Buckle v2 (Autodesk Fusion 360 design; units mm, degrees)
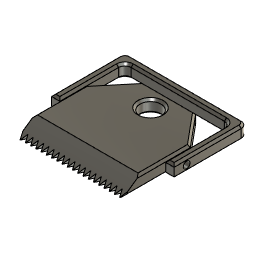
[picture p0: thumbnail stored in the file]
sketch "Sketch1" plane through (0, 0, 0) normal (0, 0, 1) x axis (1, 0, 0)
  line L1 (25, 30) -> (25, 0)
  line L2 (-25, 0) -> (-25, 30.0149)
  line L3 (-23.75, -2.5142) -> (-25, 0)
  line L4 (-22.5, 0) -> (-23.75, -2.5142)
  line L5 (-21.25, -2.5142) -> (-22.5, 0)
  line L6 (-20, 0) -> (-21.25, -2.5142)
  line L7 (-18.75, -2.5142) -> (-20, 0)
  line L8 (-17.5, 0) -> (-18.75, -2.5142)
  line L9 (-16.25, -2.5142) -> (-17.5, 0)
  line L10 (-15, 0) -> (-16.25, -2.5142)
  line L11 (-13.75, -2.5142) -> (-15, 0)
  line L12 (-12.5, 0) -> (-13.75, -2.5142)
  line L13 (-11.25, -2.5142) -> (-12.5, 0)
  line L14 (-10, 0) -> (-11.25, -2.5142)
  line L15 (-8.75, -2.5142) -> (-10, 0)
  line L16 (-7.5, 0) -> (-8.75, -2.5142)
  line L17 (-6.25, -2.5142) -> (-7.5, 0)
  line L18 (-5, 0) -> (-6.25, -2.5142)
  line L19 (-3.75, -2.5142) -> (-5, 0)
  line L20 (-2.5, 0) -> (-3.75, -2.5142)
  line L21 (-1.25, -2.5142) -> (-2.5, 0)
  line L22 (0, 0) -> (-1.25, -2.5142)
  line L23 (1.25, -2.5142) -> (0, 0)
  line L24 (2.5, 0) -> (1.25, -2.5142)
  line L25 (3.75, -2.5142) -> (2.5, 0)
  line L26 (5, 0) -> (3.75, -2.5142)
  line L27 (6.25, -2.5142) -> (5, 0)
  line L28 (7.5, 0) -> (6.25, -2.5142)
  line L29 (8.75, -2.5142) -> (7.5, 0)
  line L30 (10, 0) -> (8.75, -2.5142)
  line L31 (11.25, -2.5142) -> (10, 0)
  line L32 (12.5, 0) -> (11.25, -2.5142)
  line L33 (13.75, -2.5142) -> (12.5, 0)
  line L34 (15, 0) -> (13.75, -2.5142)
  line L35 (16.25, -2.5142) -> (15, 0)
  line L36 (17.5, 0) -> (16.25, -2.5142)
  line L37 (18.75, -2.5142) -> (17.5, 0)
  line L38 (20, 0) -> (18.75, -2.5142)
  line L39 (21.25, -2.5142) -> (20, 0)
  line L40 (22.5, 0) -> (21.25, -2.5142)
  line L41 (23.75, -2.5142) -> (22.5, 0)
  line L42 (25, 0) -> (23.75, -2.5142)
  line L43 (-12.491, 45) -> (-25, 30.0149)
  line L44 (12.509, 45) -> (-12.491, 45)
  line L45 (25, 30) -> (12.509, 45)
  circle C1 centre (-0.006, 36) radius 5
  point P66 (0.009, 45)
  point P1 (-25, 0)
  point P6 (-22.5, 0)
  point P3 (25, 30)
  point P64 (-12.491, 45)
  point P65 (12.509, 45)
  point P67 (-0.006, 36)
  point P2 (25, 0)
  vertical L1
  vertical L2
  equal L3 L4
  perpendicular L2 L44
  equal L43 L45
  midpoint L44 P66
  dimension "d1" distance P1 P6 = 2.5
  dimension "d6" distance P3 L44 = 15
  dimension "d7" distance L1 L2 = 50
  dimension "d8" distance P64 P65 = 25
  dimension "d9" diameter C1 = 10
  dimension "d10" distance P66 P67 = 9
  dimension "d11" distance P2 P3 = 30
  dimension "d4" R-Pattern1-uDistance = 47.5
  dimension "d5" R-Pattern1-vDistance = 0
extrude "Extrude1" new body sketch "Sketch1" along normal blind 6 bodies "Buckle"
sketch "Sketch2" plane through (-25, 0, 0) normal (-1, 0, 0) x axis (0, -1, 0)
  line L1 (0, 0) -> (-30.0149, 0)
  line L2 (0, 6) -> (0, 0)
  line L3 (-30.0149, 6) -> (0, 6)
  line L4 (-30.0149, 0) -> (-30.0149, 6)
  line L5 (2.5142, 0) -> (0, 0)
  line L6 (2.5142, 6) -> (2.5142, 0)
  line L7 (0, 6) -> (2.5142, 6)
  line L8 (0, 0) -> (0, 6)
  line L9 (0, 0) -> (2.5142, 0)
  line L10 (0, 6) -> (0, 0)
  line L11 (2.5142, 6) -> (0, 6)
  line L12 (2.5142, 0) -> (2.5142, 6)
  line L13 (-6.0547, 6) -> (2.5142, 0)
  line L14 (2.5142, 0) -> (-6.0547, 0)
  line L15 (-6.0547, 0) -> (-6.0547, 6)
  line L16 (2.5142, 6) -> (-6.0547, 6)
  point P7 (2.5142, 0)
  point P14 (2.5142, 0)
  point P15 (-6.0547, 6)
  point P16 (-6.0547, 0)
  point P17 (2.5142, 0)
  point P8 (2.5142, 6)
  point P18 (2.5142, 6)
  coincident P7 P14
  coincident L3 P15
  coincident L1 P16
  coincident P7 P17
  perpendicular L6 L14
  coincident P8 P18
  dimension "d14" angle L13 L14 = 35
  dimension "d15" angle L14 L15 = 90
extrude "Extrude2" cut sketch "Sketch2" profile of L2 L3 L6 L7 L8 L10 L11 L12 L13 L16 no distance stored
sketch "Sketch3" plane through (0, 0, 0) normal (0, 0, 1) x axis (1, 0, 0)
  line L1 (-25, 30.0149) -> (-25, 0)
  line L2 (-12.491, 45) -> (-25, 30.0149)
  line L3 (12.509, 45) -> (-12.491, 45)
  line L4 (25, 30) -> (12.509, 45)
  line L5 (25, 0) -> (25, 30)
  line L6 (23.75, -2.5142) -> (25, 0)
  line L7 (22.5, 0) -> (23.75, -2.5142)
  line L8 (21.25, -2.5142) -> (22.5, 0)
  line L9 (20, 0) -> (21.25, -2.5142)
  line L10 (18.75, -2.5142) -> (20, 0)
  line L11 (17.5, 0) -> (18.75, -2.5142)
  line L12 (16.25, -2.5142) -> (17.5, 0)
  line L13 (15, 0) -> (16.25, -2.5142)
  line L14 (13.75, -2.5142) -> (15, 0)
  line L15 (12.5, 0) -> (13.75, -2.5142)
  line L16 (11.25, -2.5142) -> (12.5, 0)
  line L17 (10, 0) -> (11.25, -2.5142)
  line L18 (8.75, -2.5142) -> (10, 0)
  line L19 (7.5, 0) -> (8.75, -2.5142)
  line L20 (6.25, -2.5142) -> (7.5, 0)
  line L21 (5, 0) -> (6.25, -2.5142)
  line L22 (3.75, -2.5142) -> (5, 0)
  line L23 (2.5, 0) -> (3.75, -2.5142)
  line L24 (1.25, -2.5142) -> (2.5, 0)
  line L25 (0, 0) -> (1.25, -2.5142)
  line L26 (-1.25, -2.5142) -> (0, 0)
  line L27 (-2.5, 0) -> (-1.25, -2.5142)
  line L28 (-3.75, -2.5142) -> (-2.5, 0)
  line L29 (-5, 0) -> (-3.75, -2.5142)
  line L30 (-6.25, -2.5142) -> (-5, 0)
  line L31 (-7.5, 0) -> (-6.25, -2.5142)
  line L32 (-8.75, -2.5142) -> (-7.5, 0)
  line L33 (-10, 0) -> (-8.75, -2.5142)
  line L34 (-11.25, -2.5142) -> (-10, 0)
  line L35 (-12.5, 0) -> (-11.25, -2.5142)
  line L36 (-13.75, -2.5142) -> (-12.5, 0)
  line L37 (-15, 0) -> (-13.75, -2.5142)
  line L38 (-16.25, -2.5142) -> (-15, 0)
  line L39 (-17.5, 0) -> (-16.25, -2.5142)
  line L40 (-18.75, -2.5142) -> (-17.5, 0)
  line L41 (-20, 0) -> (-18.75, -2.5142)
  line L42 (-21.25, -2.5142) -> (-20, 0)
  line L43 (-22.5, 0) -> (-21.25, -2.5142)
  line L44 (-23.75, -2.5142) -> (-22.5, 0)
  line L45 (-25, 0) -> (-23.75, -2.5142)
  line L46 (29.25, 18) -> (25.25, 18)
  line L47 (29.25, 54) -> (29.25, 18)
  line L48 (25.25, 18) -> (25.25, 49)
  line L49 (29.25, 54) -> (29.25, 53)
  line L50 (0, 49) -> (25.25, 49)
  line L51 (0, 53) -> (0, 49)
  line L52 (29.25, 53) -> (0, 53)
  line L53 (29.25, 54) -> (29.25, 53)
  line L54 (0, 72) -> (0, 0)
  line L55 (-29.25, 53) -> (0, 53)
  line L56 (0, 49) -> (-25.25, 49)
  line L57 (-25.25, 18) -> (-25.25, 49)
  line L58 (-29.25, 54) -> (-29.25, 18)
  line L59 (-29.25, 54) -> (-29.25, 53)
  line L60 (-29.25, 18) -> (-25.25, 18)
  circle C1 centre (-0.006, 36) radius 5
  point P28 (0, 0)
  point P56 (0, 0)
  point P48 (25.25, 18)
  point P62 (-25.25, 18)
  point P49 (29.25, 18)
  point P63 (-29.25, 18)
  point P50 (29.25, 54)
  point P64 (-29.25, 54)
  point P51 (25.25, 49)
  point P60 (-25.25, 49)
  point P53 (0, 49)
  point P61 (0, 49)
  point P54 (0, 53)
  point P58 (0, 53)
  point P55 (29.25, 53)
  point P59 (-29.25, 53)
  point P7 (25, 30)
  horizontal L46
  vertical L47
  vertical L48
  vertical L49
  horizontal L50
  vertical L51
  horizontal L52
  vertical L53
  coincident P28 P56
  perpendicular L52 L54
  symmetric P48 L54 P62
  symmetric P49 L54 P63
  symmetric P50 L54 P64
  symmetric P51 L54 P60
  symmetric P53 L54 P61
  symmetric P54 L54 P58
  symmetric P55 L54 P59
  dimension "d17" distance L5 L48 = 0.25
  dimension "d18" distance P7 P48 = 12
  dimension "d19" distance P48 P49 = 4
  dimension "d20" distance P53 P54 = 4
  dimension "d29" distance L3 L50 = 4
extrude "Extrude3" new body sketch "Sketch3" profile of L46 L47 L48 L49 L50 L51 L52 L53 L55 L56 L57 L58 L59 L60 to an object bodies "Hasp"
fillet "Fillet1" radius 3
chamfer "Chamfer1" distance 1
chamfer "Chamfer2" distance 1
sketch "Sketch4" plane through (0, 0, 0) normal (1, 0, 0) x axis (0, 1, 0)
  line L1 (18, 1) -> (50, 1)
  line L2 (18, 5) -> (18, 1)
  line L3 (50, 5) -> (18, 5)
  line L4 (50, 1) -> (50, 5)
  line L5 (0, 1) -> (30.0149, 1)
  line L6 (0, 1.7604) -> (0, 1)
  line L7 (4.6266, 5) -> (0, 1.7604)
  line L8 (30.0149, 5) -> (4.6266, 5)
  line L9 (30.0149, 1) -> (30.0149, 5)
  line L10 (18, 3) -> (30.0149, 3)
  circle C1 centre (24.0075, 3) radius 1.5
  circle C2 centre (24.0075, 3) radius 1.6
  circle C3 centre (24.0075, 3) radius 1.7
  point P11 (30.0149, 3)
  point P12 (18, 3)
  point P13 (24.0075, 3)
  midpoint L9 P11
  midpoint L2 P12
  midpoint L10 P13
  dimension "d31" = 0.1
  dimension "d33" diameter C1 = 3
  dimension "d34" = 0.2
extrude "Extrude4" cut sketch "Sketch4" profile of L1 L3 L5 L8 C1 C2 no distance stored
chamfer "Chamfer3" distance 1
extrude "Extrude5" cut sketch "Sketch4" profile of C1 C2 C3 no distance stored
named bodies: "Buckle", "Hasp"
